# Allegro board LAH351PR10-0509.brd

Outline 153 x 157 mm; copper layers: TOP, GND1, IN1, GND2, IN2, GND3, VCC, IN3, GND4, IN4, GND5, BOTTOM. Coordinates in mm from the lower left corner of the outline.
Outline path: 0,137.03 arc(0.01,137.4) 0.03,137.76 0.37,141.89 arc(0.52,142.22) 0.86,142.35 2,142.35 arc(3.25,143.6) 2,144.85 1.15,144.85 arc(0.78,145.01) 0.65,145.39 0.66,145.54 arc(0.82,145.87) 1.16,146 4.55,146 arc(4.84,145.96) 5.1,145.84 11.6,141.56 arc(11.86,141.44) 12.15,141.4 23.59,141.4 arc(23.78,141.44) 23.95,141.55 26.65,144.25 arc(26.76,144.42) 26.8,144.61 26.8,156.5 arc(26.95,156.85) 27.3,157 31.55,157 arc(31.89,156.87) 32.05,156.55 arc(32.21,156.23) 32.55,156.1 57.55,156.1 arc(57.89,156.23) 58.05,156.55 arc(58.21,156.87) 58.55,157 62.4,157 arc(62.75,156.85) 62.9,156.5 62.9,152.5 arc(63.05,152.15) 63.4,152 74.77,152 arc(74.9,152.02) 75.02,152.07 83.44,156.93 arc(83.56,156.98) 83.69,157 143.8,157 arc(144.15,156.85) 144.3,156.5 144.3,151.4 arc(144.15,151.05) 143.8,150.9 142.89,150.9 arc(141.59,149.6) 142.89,148.3 143.8,148.3 arc(144.15,148.15) 144.3,147.8 144.3,147 arc(144.45,146.65) 144.8,146.5 152.5,146.5 arc(152.85,146.35) 153,146 153,20.2 arc(152.85,19.85) 152.5,19.7 140.7,19.7 arc(140.35,19.55) 140.2,19.2 140.2,2.69 arc(140.05,2.33) 139.7,2.18 138.52,2.18 arc(138.17,2.33) 138.03,2.69 138.03,6.55 arc(138.07,6.7) 138.18,6.81 arc(138.24,7.28) 137.77,7.22 arc(137.66,7.11) 137.51,7.07 117.29,7.07 arc(117.14,7.11) 117.03,7.22 arc(116.56,7.28) 116.62,6.81 arc(116.73,6.7) 116.77,6.55 116.77,2.69 arc(116.63,2.33) 116.28,2.18 113.72,2.18 arc(113.37,2.33) 113.23,2.69 113.23,6.55 arc(113.27,6.7) 113.38,6.81 arc(113.44,7.28) 112.97,7.22 arc(112.86,7.11) 112.71,7.07 92.49,7.07 arc(92.34,7.11) 92.23,7.22 arc(91.76,7.28) 91.82,6.81 arc(91.93,6.7) 91.97,6.55 91.97,2.69 arc(91.85,2.35) 91.54,2.19 arc(91.22,2.02) 91.1,1.69 91.1,0.5 arc(90.95,0.15) 90.6,0 0.5,0 arc(0.15,0.15) 0,0.5 0,137.03 ; 85.5,2.5 arc(87,4) 88.5,2.5 88.5,1.7 arc(88.35,1.35) 88,1.2 86,1.2 arc(85.65,1.35) 85.5,1.7 85.5,2.5

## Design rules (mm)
net group ADC_IN_: nets ADC_IN_N ADC_IN_P
net group ADC_IN__RC: nets ADC_IN_N_RC ADC_IN_P_RC
net group CDRA_: nets CDRA_CLK CDRA_DAT
net group CORE_V1: nets CORE_V1N CORE_V1P
net group CORE_V2: nets CORE_V2N CORE_V2P
net group CORE_V3: nets CORE_V3N CORE_V3P
net group CORE_V4: nets CORE_V4N CORE_V4P
net group CORE_V5: nets CORE_V5N CORE_V5P
net group CORE_V6: nets CORE_V6N CORE_V6P
net group CPU_DDC1: nets CPU_DDC1CLK CPU_DDC1DATA
net group CSI_CHG: nets CSIN_CHG CSIP_CHG
net group CSO_CHG: nets CSON_CHG CSOP_CHG
net group CSS_B+: nets CSSN_B+ CSSP_B+
net group DDR-ALERT_8: nets DDR_A_ALERT# DDR_B_ALERT#
net group DDR_RST: nets DDR_DRAMRST#_R H_DRAMRST#
net group DDRB-CLK: nets DDR_B_CLK0 DDR_B_CLK#0
net group DIFFPAIR1: nets XTALIN XTALOUT
net group DIFFPAIR120: nets CPU_DDC2CLK CPU_DDC2DATA
net group DIFFPAIR121: nets EDP_TXN0_PCH EDP_TXP0_PCH
net group DIFFPAIR122: nets EDP_TXN1_PCH EDP_TXP1_PCH
net group DIFFPAIR123: nets EDP_TXN2_PCH EDP_TXP2_PCH
net group DIFFPAIR124: nets EDP_AUXN_PCH EDP_AUXP_PCH
net group DIFFPAIR125: nets EDP_TXN3_PCH EDP_TXP3_PCH
net group DIFFPAIR126: nets DDR_A_CLK0 DDR_A_CLK#0
net group EC_ESB_: nets EC_ESB_CLK EC_ESB_DAT
net group HDMI_CTRL_: nets HDMI_CTRL_CLK HDMI_CTRL_DAT
net group HDMI_CTRL__R: nets HDMI_CTRL_CLK_R HDMI_CTRL_DAT_R
net group I2C: nets TBTA_I2C_INT TBTA_I2C_INT_R
net group I2C_: nets I2C_CLK I2C_DAT
net group I2C_0_S: nets I2C_0_SCL I2C_0_SDA
net group I2C_0_S_R: nets I2C_0_SCL_R I2C_0_SDA_R
net group I2CC_S: nets I2CC_SCL I2CC_SDA
net group ISEN1_CHG: nets ISEN1N_CHG ISEN1P_CHG
net group ISH_I2C0_S: nets ISH_I2C0_SCL ISH_I2C0_SDA
net group ISL95338_S: nets ISL95338_SCL ISL95338_SDA
net group MIC_: nets MIC_CLK MIC_DATA
net group PCH_CPU_BCLK_: nets PCH_CPU_BCLK_N PCH_CPU_BCLK_P
net group PCH_SMB: nets PCH_SMBCLK PCH_SMBDATA
net group PCIE_RCOMP: nets PCIE_RCOMPN PCIE_RCOMPP
net group PEG_CLK: nets CLK_PEG_N0 CLK_PEG_P0
net group REMOTE1: nets REMOTE1+ REMOTE1-
net group REMOTE2: nets REMOTE2+ REMOTE2-
net group REMOTE3: nets REMOTE3+ REMOTE3-
net group S_CHG: nets SCL_CHG SDA_CHG
net group S_GPU: nets SCL_GPU SDA_GPU
net group SH_IN_3: nets SH_IN_N3 SH_IN_P3
net group SH_IN_4: nets SH_IN_N4 SH_IN_P4
net group SML0: nets SML0CLK SML0DATA
net group SML1: nets SML1CLK SML1DATA
net group TBT_I2C_S: nets TBT_I2C_SCL TBT_I2C_SDA
net group TBT_I2C_S_R: nets TBT_I2C_SCL_R TBT_I2C_SDA_R
net group TBTA_DIG_AUD_: nets TBTA_DIG_AUD_N TBTA_DIG_AUD_P
net group TBTA_I2C_S1_R: nets TBTA_I2C_SCL1_R TBTA_I2C_SDA1_R
net group TP_: nets TP_CLK TP_DATA
net group TP__R: nets TP_CLK_R TP_DATA_R
net group UART: nets UART_2_PRXD_DTXD UART_2_PTXD_DRXD
net group USB20_N3: nets USB20_N3 USB20_N3_R
net group USB20_P3: nets USB20_P3 USB20_P3_R
net group VIN1: nets VIN1N VIN1P
net group VIN2: nets VIN2N VIN2P
net group DDR_COMP: nets DDR_RCOMP0 DDR_RCOMP1 DDR_RCOMP2
net group DDRA-D0: nets DDR_A_D0 DDR_A_D1 DDR_A_D2 DDR_A_D3 DDR_A_D4 DDR_A_D5 DDR_A_D6 DDR_A_D7
net group DDRA-D1: nets DDR_A_D8 DDR_A_D9 DDR_A_D10 DDR_A_D11 DDR_A_D12 DDR_A_D13 DDR_A_D14 DDR_A_D15
net group DDRA-D2: nets DDR_A_D16 DDR_A_D17 DDR_A_D18 DDR_A_D19 DDR_A_D20 DDR_A_D21 DDR_A_D22 DDR_A_D23
net group DDRA-D3: nets DDR_A_D24 DDR_A_D25 DDR_A_D26 DDR_A_D27 DDR_A_D28 DDR_A_D29 DDR_A_D30 DDR_A_D31
net group DDRA-D4: nets DDR_A_D32 DDR_A_D33 DDR_A_D34 DDR_A_D35 DDR_A_D36 DDR_A_D37 DDR_A_D38 DDR_A_D39
net group DDRA-D5: nets DDR_A_D40 DDR_A_D41 DDR_A_D42 DDR_A_D43 DDR_A_D44 DDR_A_D45 DDR_A_D46 DDR_A_D47
net group DDRA-D6: nets DDR_A_D48 DDR_A_D49 DDR_A_D50 DDR_A_D51 DDR_A_D52 DDR_A_D53 DDR_A_D54 DDR_A_D55
net group DDRA-D7: nets DDR_A_D56 DDR_A_D57 DDR_A_D58 DDR_A_D59 DDR_A_D60 DDR_A_D61 DDR_A_D62 DDR_A_D63
net group DDRA-DQS: nets DDR_A_DQS0 DDR_A_DQS1 DDR_A_DQS2 DDR_A_DQS3 DDR_A_DQS4 DDR_A_DQS5 DDR_A_DQS6 DDR_A_DQS7 DDR_A_DQS#0 DDR_A_DQS#1 DDR_A_DQS#2 DDR_A_DQS#3 DDR_A_DQS#4 DDR_A_DQS#5 DDR_A_DQS#6 DDR_A_DQS#7
net group DDRA_ADD: nets DDR_A_ACT# DDR_A_BA0 DDR_A_BA1 DDR_A_BG0 DDR_A_BG1 DDR_A_MA0 DDR_A_MA1 DDR_A_MA2 DDR_A_MA3 DDR_A_MA4 DDR_A_MA5 DDR_A_MA6 DDR_A_MA7 DDR_A_MA8 DDR_A_MA9 DDR_A_MA10 DDR_A_MA11 DDR_A_MA12 DDR_A_MA13 DDR_A_MA14 DDR_A_MA15 DDR_A_MA16 DDR_A_PARITY
net group DDRA_CTRL: nets DDR_A_CKE0 DDR_A_CS#0 DDR_A_ODT0
net group DDRB-D0: nets DDR_B_D0 DDR_B_D1 DDR_B_D2 DDR_B_D3 DDR_B_D4 DDR_B_D5 DDR_B_D6 DDR_B_D7
net group DDRB-D1: nets DDR_B_D8 DDR_B_D9 DDR_B_D10 DDR_B_D11 DDR_B_D12 DDR_B_D13 DDR_B_D14 DDR_B_D15
net group DDRB-D2: nets DDR_B_D16 DDR_B_D17 DDR_B_D18 DDR_B_D19 DDR_B_D20 DDR_B_D21 DDR_B_D22 DDR_B_D23
net group DDRB-D3: nets DDR_B_D24 DDR_B_D25 DDR_B_D26 DDR_B_D27 DDR_B_D28 DDR_B_D29 DDR_B_D30 DDR_B_D31
net group DDRB-D4: nets DDR_B_D32 DDR_B_D33 DDR_B_D34 DDR_B_D35 DDR_B_D36 DDR_B_D37 DDR_B_D38 DDR_B_D39
net group DDRB-D5: nets DDR_B_D40 DDR_B_D41 DDR_B_D42 DDR_B_D43 DDR_B_D44 DDR_B_D45 DDR_B_D46 DDR_B_D47
net group DDRB-D6: nets DDR_B_D48 DDR_B_D49 DDR_B_D50 DDR_B_D51 DDR_B_D52 DDR_B_D53 DDR_B_D54 DDR_B_D55
net group DDRB-D7: nets DDR_B_D56 DDR_B_D57 DDR_B_D58 DDR_B_D59 DDR_B_D60 DDR_B_D61 DDR_B_D62 DDR_B_D63
net group DDRB-DQS: nets DDR_B_DQS0 DDR_B_DQS1 DDR_B_DQS2 DDR_B_DQS3 DDR_B_DQS4 DDR_B_DQS5 DDR_B_DQS6 DDR_B_DQS7 DDR_B_DQS#0 DDR_B_DQS#1 DDR_B_DQS#2 DDR_B_DQS#3 DDR_B_DQS#4 DDR_B_DQS#5 DDR_B_DQS#6 DDR_B_DQS#7
net group DDRB_ADD: nets DDR_B_ACT# DDR_B_BA0 DDR_B_BA1 DDR_B_BG0 DDR_B_BG1 DDR_B_MA0 DDR_B_MA1 DDR_B_MA2 DDR_B_MA3 DDR_B_MA4 DDR_B_MA5 DDR_B_MA6 DDR_B_MA7 DDR_B_MA8 DDR_B_MA9 DDR_B_MA10 DDR_B_MA11 DDR_B_MA12 DDR_B_MA13 DDR_B_MA14 DDR_B_MA15 DDR_B_MA16 DDR_B_PARITY
net group DDRB_CTRL: nets DDR_B_CKE0 DDR_B_CS#0 DDR_B_ODT0
net group DMI: nets DMI_CRX_PTX_N0 DMI_CRX_PTX_N1 DMI_CRX_PTX_N2 DMI_CRX_PTX_N3 DMI_CRX_PTX_P0 DMI_CRX_PTX_P1 DMI_CRX_PTX_P2 DMI_CRX_PTX_P3 DMI_CTX_PRX_N0 DMI_CTX_PRX_N1 DMI_CTX_PRX_N2 DMI_CTX_PRX_N3 DMI_CTX_PRX_P0 DMI_CTX_PRX_P1 DMI_CTX_PRX_P2 DMI_CTX_PRX_P3
net group DP: nets CPU_DP1_AUXN CPU_DP1_AUXN_C CPU_DP1_AUXP CPU_DP1_AUXP_C CPU_DP1_HPD CPU_DP1_N0 CPU_DP1_N0_C CPU_DP1_N1 CPU_DP1_N1_C CPU_DP1_N2 CPU_DP1_N2_C CPU_DP1_N3 CPU_DP1_N3_C CPU_DP1_P0 CPU_DP1_P0_C CPU_DP1_P1 CPU_DP1_P1_C CPU_DP1_P2 CPU_DP1_P2_C CPU_DP1_P3 CPU_DP1_P3_C CPU_DP2_AUXN CPU_DP2_AUXN_C CPU_DP2_AUXP CPU_DP2_AUXP_C CPU_DP2_HPD CPU_DP2_N0 CPU_DP2_N0_C CPU_DP2_N1 CPU_DP2_N1_C CPU_DP2_N2 CPU_DP2_N2_C CPU_DP2_N3 CPU_DP2_N3_C CPU_DP2_P0 CPU_DP2_P0_C CPU_DP2_P1 CPU_DP2_P1_C CPU_DP2_P2 CPU_DP2_P2_C CPU_DP2_P3 CPU_DP2_P3_C
net group EDP: nets EDP_AUXN_C EDP_AUXP_C EDP_TXN0_C EDP_TXN1_C EDP_TXN2_C EDP_TXN3_C EDP_TXP0_C EDP_TXP1_C EDP_TXP2_C EDP_TXP3_C
net group GPU_A_CLK: nets FB_A_CLK0 FB_A_CLK1 FB_A_CLK#0 FB_A_CLK#1
net group GPU_A_CMD: nets FB_A_CMD0 FB_A_CMD1 FB_A_CMD2 FB_A_CMD3 FB_A_CMD4 FB_A_CMD5 FB_A_CMD6 FB_A_CMD7 FB_A_CMD8 FB_A_CMD9 FB_A_CMD10 FB_A_CMD11 FB_A_CMD12 FB_A_CMD13 FB_A_CMD14 FB_A_CMD15 FB_A_CMD16 FB_A_CMD17 FB_A_CMD18 FB_A_CMD19 FB_A_CMD20 FB_A_CMD21 FB_A_CMD22 FB_A_CMD23 FB_A_CMD24 FB_A_CMD25 FB_A_CMD26 FB_A_CMD27 FB_A_CMD28 FB_A_CMD29 FB_A_CMD30 FB_A_CMD31 FB_A_CMD32 FB_A_CMD33
net group GPU_A_D0: nets FB_A_D0 FB_A_D1 FB_A_D2 FB_A_D3 FB_A_D4 FB_A_D5 FB_A_D6 FB_A_D7
net group GPU_A_D1: nets FB_A_D8 FB_A_D9 FB_A_D10 FB_A_D11 FB_A_D12 FB_A_D13 FB_A_D14 FB_A_D15
net group GPU_A_D2: nets FB_A_D16 FB_A_D17 FB_A_D18 FB_A_D19 FB_A_D20 FB_A_D21 FB_A_D22 FB_A_D23
net group GPU_A_D3: nets FB_A_D24 FB_A_D25 FB_A_D26 FB_A_D27 FB_A_D28 FB_A_D29 FB_A_D30 FB_A_D31
net group GPU_A_D4: nets FB_A_D32 FB_A_D33 FB_A_D34 FB_A_D35 FB_A_D36 FB_A_D37 FB_A_D38 FB_A_D39
net group GPU_A_D5: nets FB_A_D40 FB_A_D41 FB_A_D42 FB_A_D43 FB_A_D44 FB_A_D45 FB_A_D46 FB_A_D47
net group GPU_A_D6: nets FB_A_D48 FB_A_D49 FB_A_D50 FB_A_D51 FB_A_D52 FB_A_D53 FB_A_D54 FB_A_D55
net group GPU_A_D7: nets FB_A_D56 FB_A_D57 FB_A_D58 FB_A_D59 FB_A_D60 FB_A_D61 FB_A_D62 FB_A_D63
net group GPU_A_DBI: nets FB_A_DBI0 FB_A_DBI1 FB_A_DBI2 FB_A_DBI3 FB_A_DBI4 FB_A_DBI5 FB_A_DBI6 FB_A_DBI7
net group GPU_A_EDC: nets FB_A_EDC0 FB_A_EDC1 FB_A_EDC2 FB_A_EDC3 FB_A_EDC4 FB_A_EDC5 FB_A_EDC6 FB_A_EDC7
net group GPU_A_WCK: nets FB_A_WCK01 FB_A_WCK23 FB_A_WCK45 FB_A_WCK67 FB_A_WCK#01 FB_A_WCK#23 FB_A_WCK#45 FB_A_WCK#67 FB_A_WCKB01 FB_A_WCKB23 FB_A_WCKB45 FB_A_WCKB67 FB_A_WCKB#01 FB_A_WCKB#23 FB_A_WCKB#45 FB_A_WCKB#67
net group GPU_B_CLK: nets FB_B_CLK0 FB_B_CLK1 FB_B_CLK#0 FB_B_CLK#1
net group GPU_B_CMD: nets FB_B_CMD0 FB_B_CMD1 FB_B_CMD2 FB_B_CMD3 FB_B_CMD4 FB_B_CMD5 FB_B_CMD6 FB_B_CMD7 FB_B_CMD8 FB_B_CMD9 FB_B_CMD10 FB_B_CMD11 FB_B_CMD12 FB_B_CMD13 FB_B_CMD14 FB_B_CMD15 FB_B_CMD16 FB_B_CMD17 FB_B_CMD18 FB_B_CMD19 FB_B_CMD20 FB_B_CMD21 FB_B_CMD22 FB_B_CMD23 FB_B_CMD24 FB_B_CMD25 FB_B_CMD26 FB_B_CMD27 FB_B_CMD28 FB_B_CMD29 FB_B_CMD30 FB_B_CMD31 FB_B_CMD32 FB_B_CMD33
net group GPU_B_D0: nets FB_B_D0 FB_B_D1 FB_B_D2 FB_B_D3 FB_B_D4 FB_B_D5 FB_B_D6 FB_B_D7
net group GPU_B_D1: nets FB_B_D8 FB_B_D9 FB_B_D10 FB_B_D11 FB_B_D12 FB_B_D13 FB_B_D14 FB_B_D15
net group GPU_B_D2: nets FB_B_D16 FB_B_D17 FB_B_D18 FB_B_D19 FB_B_D20 FB_B_D21 FB_B_D22 FB_B_D23
net group GPU_B_D3: nets FB_B_D24 FB_B_D25 FB_B_D26 FB_B_D27 FB_B_D28 FB_B_D29 FB_B_D30 FB_B_D31
net group GPU_B_D4: nets FB_B_D32 FB_B_D33 FB_B_D34 FB_B_D35 FB_B_D36 FB_B_D37 FB_B_D38 FB_B_D39
net group GPU_B_D5: nets FB_B_D40 FB_B_D41 FB_B_D42 FB_B_D43 FB_B_D44 FB_B_D45 FB_B_D46 FB_B_D47
net group GPU_B_D6: nets FB_B_D48 FB_B_D49 FB_B_D50 FB_B_D51 FB_B_D52 FB_B_D53 FB_B_D54 FB_B_D55
net group GPU_B_D7: nets FB_B_D56 FB_B_D57 FB_B_D58 FB_B_D59 FB_B_D60 FB_B_D61 FB_B_D62 FB_B_D63
net group GPU_B_DBI: nets FB_B_DBI0 FB_B_DBI1 FB_B_DBI2 FB_B_DBI3 FB_B_DBI4 FB_B_DBI5 FB_B_DBI6 FB_B_DBI7
net group GPU_B_EDC: nets FB_B_EDC0 FB_B_EDC1 FB_B_EDC2 FB_B_EDC3 FB_B_EDC4 FB_B_EDC5 FB_B_EDC6 FB_B_EDC7
net group GPU_B_WCK: nets FB_B_WCK01 FB_B_WCK23 FB_B_WCK45 FB_B_WCK67 FB_B_WCK#01 FB_B_WCK#23 FB_B_WCK#45 FB_B_WCK#67
net group GPU_C_CLK: nets FB_C_CLK0 FB_C_CLK1 FB_C_CLK#0 FB_C_CLK#1
net group GPU_C_CMD: nets FB_C_CMD0 FB_C_CMD1 FB_C_CMD2 FB_C_CMD3 FB_C_CMD4 FB_C_CMD5 FB_C_CMD6 FB_C_CMD7 FB_C_CMD8 FB_C_CMD9 FB_C_CMD10 FB_C_CMD11 FB_C_CMD12 FB_C_CMD13 FB_C_CMD14 FB_C_CMD15 FB_C_CMD16 FB_C_CMD17 FB_C_CMD18 FB_C_CMD19 FB_C_CMD20 FB_C_CMD21 FB_C_CMD22 FB_C_CMD23 FB_C_CMD24 FB_C_CMD25 FB_C_CMD26 FB_C_CMD27 FB_C_CMD28 FB_C_CMD29 FB_C_CMD30 FB_C_CMD31 FB_C_CMD32 FB_C_CMD33
net group GPU_C_D0: nets FB_C_D0 FB_C_D1 FB_C_D2 FB_C_D3 FB_C_D4 FB_C_D5 FB_C_D6 FB_C_D7
net group GPU_C_D1: nets FB_C_D8 FB_C_D9 FB_C_D10 FB_C_D11 FB_C_D12 FB_C_D13 FB_C_D14 FB_C_D15
net group GPU_C_D2: nets FB_C_D16 FB_C_D17 FB_C_D18 FB_C_D19 FB_C_D20 FB_C_D21 FB_C_D22 FB_C_D23
net group GPU_C_D3: nets FB_C_D24 FB_C_D25 FB_C_D26 FB_C_D27 FB_C_D28 FB_C_D29 FB_C_D30 FB_C_D31
net group GPU_C_D4: nets FB_C_D32 FB_C_D33 FB_C_D34 FB_C_D35 FB_C_D36 FB_C_D37 FB_C_D38 FB_C_D39
net group GPU_C_D5: nets FB_C_D40 FB_C_D41 FB_C_D42 FB_C_D43 FB_C_D44 FB_C_D45 FB_C_D46 FB_C_D47
net group GPU_C_D6: nets FB_C_D48 FB_C_D49 FB_C_D50 FB_C_D51 FB_C_D52 FB_C_D53 FB_C_D54 FB_C_D55
net group GPU_C_D7: nets FB_C_D56 FB_C_D57 FB_C_D58 FB_C_D59 FB_C_D60 FB_C_D61 FB_C_D62 FB_C_D63
net group GPU_C_DBI: nets FB_C_DBI0 FB_C_DBI1 FB_C_DBI2 FB_C_DBI3 FB_C_DBI4 FB_C_DBI5 FB_C_DBI6 FB_C_DBI7
net group GPU_C_EDC: nets FB_C_EDC0 FB_C_EDC1 FB_C_EDC2 FB_C_EDC3 FB_C_EDC4 FB_C_EDC5 FB_C_EDC6 FB_C_EDC7
net group GPU_C_WCK: nets FB_B_WCKB01 FB_B_WCKB23 FB_B_WCKB45 FB_B_WCKB67 FB_B_WCKB#01 FB_B_WCKB#23 FB_B_WCKB#45 FB_B_WCKB#67 FB_C_WCK01 FB_C_WCK23 FB_C_WCK45 FB_C_WCK67 FB_C_WCK#01 FB_C_WCK#23 FB_C_WCK#45 FB_C_WCK#67 FB_C_WCKB01 FB_C_WCKB23 FB_C_WCKB45 FB_C_WCKB67 FB_C_WCKB#01 FB_C_WCKB#23 FB_C_WCKB#45 FB_C_WCKB#67
net group GPU_D_CLK: nets FB_D_CLK0 FB_D_CLK1 FB_D_CLK#0 FB_D_CLK#1
net group GPU_D_CMD: nets FB_D_CMD0 FB_D_CMD1 FB_D_CMD2 FB_D_CMD3 FB_D_CMD4 FB_D_CMD5 FB_D_CMD6 FB_D_CMD7 FB_D_CMD8 FB_D_CMD9 FB_D_CMD10 FB_D_CMD11 FB_D_CMD12 FB_D_CMD13 FB_D_CMD14 FB_D_CMD15 FB_D_CMD16 FB_D_CMD17 FB_D_CMD18 FB_D_CMD19 FB_D_CMD20 FB_D_CMD21 FB_D_CMD22 FB_D_CMD23 FB_D_CMD24 FB_D_CMD25 FB_D_CMD26 FB_D_CMD27 FB_D_CMD28 FB_D_CMD29 FB_D_CMD30 FB_D_CMD31 FB_D_CMD32 FB_D_CMD33
net group GPU_D_D0: nets FB_D_D0 FB_D_D1 FB_D_D2 FB_D_D3 FB_D_D4 FB_D_D5 FB_D_D6 FB_D_D7
net group GPU_D_D1: nets FB_D_D8 FB_D_D9 FB_D_D10 FB_D_D11 FB_D_D12 FB_D_D13 FB_D_D14 FB_D_D15
net group GPU_D_D2: nets FB_D_D16 FB_D_D17 FB_D_D18 FB_D_D19 FB_D_D20 FB_D_D21 FB_D_D22 FB_D_D23
net group GPU_D_D3: nets FB_D_D24 FB_D_D25 FB_D_D26 FB_D_D27 FB_D_D28 FB_D_D29 FB_D_D30 FB_D_D31
net group GPU_D_D4: nets FB_D_D32 FB_D_D33 FB_D_D34 FB_D_D35 FB_D_D36 FB_D_D37 FB_D_D38 FB_D_D39
net group GPU_D_D5: nets FB_D_D40 FB_D_D41 FB_D_D42 FB_D_D43 FB_D_D44 FB_D_D45 FB_D_D46 FB_D_D47
net group GPU_D_D6: nets FB_D_D48 FB_D_D49 FB_D_D50 FB_D_D51 FB_D_D52 FB_D_D53 FB_D_D54 FB_D_D55
net group GPU_D_D7: nets FB_D_D56 FB_D_D57 FB_D_D58 FB_D_D59 FB_D_D60 FB_D_D61 FB_D_D62 FB_D_D63
net group GPU_D_DBI: nets FB_D_DBI0 FB_D_DBI1 FB_D_DBI2 FB_D_DBI3 FB_D_DBI4 FB_D_DBI5 FB_D_DBI6 FB_D_DBI7
net group GPU_D_EDC: nets FB_D_EDC0 FB_D_EDC1 FB_D_EDC2 FB_D_EDC3 FB_D_EDC4 FB_D_EDC5 FB_D_EDC6 FB_D_EDC7
net group GPU_D_WCK: nets FB_D_WCK01 FB_D_WCK23 FB_D_WCK45 FB_D_WCK67 FB_D_WCK#01 FB_D_WCK#23 FB_D_WCK#45 FB_D_WCK#67 FB_D_WCKB01 FB_D_WCKB23 FB_D_WCKB45 FB_D_WCKB67 FB_D_WCKB#01 FB_D_WCKB#23 FB_D_WCKB#45 FB_D_WCKB#67
net group HDA: nets HDA_BIT_CLK HDA_BIT_CLK_R HDA_RST# HDA_RST#_R HDA_SDIN HDA_SDOUT HDA_SDOUT_R HDA_SYNC HDA_SYNC_R
net group HDMI: nets GPU_HDMI_CLKN GPU_HDMI_CLKP GPU_HDMI_CTRL_CLK GPU_HDMI_CTRL_DAT GPU_HDMI_TX_N0 GPU_HDMI_TX_N1 GPU_HDMI_TX_N2 GPU_HDMI_TX_P0 GPU_HDMI_TX_P1 GPU_HDMI_TX_P2 HDMI_C_CLKN HDMI_C_CLKP HDMI_C_TX_N0 HDMI_C_TX_N1 HDMI_C_TX_N2 HDMI_C_TX_P0 HDMI_C_TX_P1 HDMI_C_TX_P2 HDMI_CLKN HDMI_CLKP HDMI_L_CLKN HDMI_L_CLKP HDMI_L_TX_N0 HDMI_L_TX_N1 HDMI_L_TX_N2 HDMI_L_TX_P0 HDMI_L_TX_P1 HDMI_L_TX_P2 HDMI_TX_N0 HDMI_TX_N1 HDMI_TX_N2 HDMI_TX_P0 HDMI_TX_P1 HDMI_TX_P2
net group MDP: nets DISP_CLK_AUXP_CONN DISP_DAT_AUXN_CONN GPU_DP_AUXN GPU_DP_AUXN_C GPU_DP_AUXN_R GPU_DP_AUXP GPU_DP_AUXP_C GPU_DP_AUXP_R GPU_DP_N0 GPU_DP_N0_C GPU_DP_N1 GPU_DP_N1_C GPU_DP_N2 GPU_DP_N2_C GPU_DP_N3 GPU_DP_N3_C GPU_DP_P0 GPU_DP_P0_C GPU_DP_P1 GPU_DP_P1_C GPU_DP_P2 GPU_DP_P2_C GPU_DP_P3 GPU_DP_P3_C
net group PCIE: nets PCIE_PRX_C_DTX_N17 PCIE_PRX_C_DTX_N18 PCIE_PRX_C_DTX_N19 PCIE_PRX_C_DTX_N20 PCIE_PRX_C_DTX_P17 PCIE_PRX_C_DTX_P18 PCIE_PRX_C_DTX_P19 PCIE_PRX_C_DTX_P20 PCIE_PRX_DTX_N9 PCIE_PRX_DTX_N10 PCIE_PRX_DTX_N11 PCIE_PRX_DTX_N12 PCIE_PRX_DTX_N15 PCIE_PRX_DTX_N16 PCIE_PRX_DTX_N17 PCIE_PRX_DTX_N18 PCIE_PRX_DTX_N19 PCIE_PRX_DTX_N20 PCIE_PRX_DTX_N21 PCIE_PRX_DTX_N22 PCIE_PRX_DTX_N23 PCIE_PRX_DTX_N24 PCIE_PRX_DTX_P9 PCIE_PRX_DTX_P10 PCIE_PRX_DTX_P11 PCIE_PRX_DTX_P12 PCIE_PRX_DTX_P15 PCIE_PRX_DTX_P16 PCIE_PRX_DTX_P17 PCIE_PRX_DTX_P18 PCIE_PRX_DTX_P19 PCIE_PRX_DTX_P20 PCIE_PRX_DTX_P21 PCIE_PRX_DTX_P22 PCIE_PRX_DTX_P23 PCIE_PRX_DTX_P24 PCIE_PTX_C_DRX_N9 PCIE_PTX_C_DRX_N10 PCIE_PTX_C_DRX_N11 PCIE_PTX_C_DRX_N12 PCIE_PTX_C_DRX_N17 PCIE_PTX_C_DRX_N18 PCIE_PTX_C_DRX_N19 PCIE_PTX_C_DRX_N20 PCIE_PTX_C_DRX_N21 PCIE_PTX_C_DRX_N22 PCIE_PTX_C_DRX_N23 PCIE_PTX_C_DRX_N24 PCIE_PTX_C_DRX_P9 PCIE_PTX_C_DRX_P10 PCIE_PTX_C_DRX_P11 PCIE_PTX_C_DRX_P12 PCIE_PTX_C_DRX_P17 PCIE_PTX_C_DRX_P18 PCIE_PTX_C_DRX_P19 PCIE_PTX_C_DRX_P20 PCIE_PTX_C_DRX_P21 PCIE_PTX_C_DRX_P22 PCIE_PTX_C_DRX_P23 PCIE_PTX_C_DRX_P24 PCIE_PTX_DRX_N9 PCIE_PTX_DRX_N10 PCIE_PTX_DRX_N11 PCIE_PTX_DRX_N12 PCIE_PTX_DRX_N15 PCIE_PTX_DRX_N16 PCIE_PTX_DRX_N17 PCIE_PTX_DRX_N18 PCIE_PTX_DRX_N19 PCIE_PTX_DRX_N20 PCIE_PTX_DRX_N21 PCIE_PTX_DRX_N22 PCIE_PTX_DRX_N23 PCIE_PTX_DRX_N24 PCIE_PTX_DRX_P9 PCIE_PTX_DRX_P10 PCIE_PTX_DRX_P11 PCIE_PTX_DRX_P12 PCIE_PTX_DRX_P15 PCIE_PTX_DRX_P16 PCIE_PTX_DRX_P17 PCIE_PTX_DRX_P18 PCIE_PTX_DRX_P19 PCIE_PTX_DRX_P20 PCIE_PTX_DRX_P21 PCIE_PTX_DRX_P22 PCIE_PTX_DRX_P23 PCIE_PTX_DRX_P24
net group PEG: nets PEG_CRX_C_GTX_N0 PEG_CRX_C_GTX_N1 PEG_CRX_C_GTX_N2 PEG_CRX_C_GTX_N3 PEG_CRX_C_GTX_N4 PEG_CRX_C_GTX_N5 PEG_CRX_C_GTX_N6 PEG_CRX_C_GTX_N7 PEG_CRX_C_GTX_P0 PEG_CRX_C_GTX_P1 PEG_CRX_C_GTX_P2 PEG_CRX_C_GTX_P3 PEG_CRX_C_GTX_P4 PEG_CRX_C_GTX_P5 PEG_CRX_C_GTX_P6 PEG_CRX_C_GTX_P7 PEG_CRX_C_RD_GTX_N8 PEG_CRX_C_RD_GTX_N9 PEG_CRX_C_RD_GTX_N10 PEG_CRX_C_RD_GTX_N11 PEG_CRX_C_RD_GTX_P8 PEG_CRX_C_RD_GTX_P9 PEG_CRX_C_RD_GTX_P10 PEG_CRX_C_RD_GTX_P11 PEG_CRX_GTX_N0 PEG_CRX_GTX_N1 PEG_CRX_GTX_N2 PEG_CRX_GTX_N3 PEG_CRX_GTX_N4 PEG_CRX_GTX_N5 PEG_CRX_GTX_N6 PEG_CRX_GTX_N7 PEG_CRX_GTX_N8 PEG_CRX_GTX_N9 PEG_CRX_GTX_N10 PEG_CRX_GTX_N11 PEG_CRX_GTX_P0 PEG_CRX_GTX_P1 PEG_CRX_GTX_P2 PEG_CRX_GTX_P3 PEG_CRX_GTX_P4 PEG_CRX_GTX_P5 PEG_CRX_GTX_P6 PEG_CRX_GTX_P7 PEG_CRX_GTX_P8 PEG_CRX_GTX_P9 PEG_CRX_GTX_P10 PEG_CRX_GTX_P11 PEG_CRX_RD_GTX_N8 PEG_CRX_RD_GTX_N9 PEG_CRX_RD_GTX_N10 PEG_CRX_RD_GTX_N11 PEG_CRX_RD_GTX_P8 PEG_CRX_RD_GTX_P9 PEG_CRX_RD_GTX_P10 PEG_CRX_RD_GTX_P11 PEG_CTX_C_GRX_N0 PEG_CTX_C_GRX_N1 PEG_CTX_C_GRX_N2 PEG_CTX_C_GRX_N3 PEG_CTX_C_GRX_N4 PEG_CTX_C_GRX_N5 PEG_CTX_C_GRX_N6 PEG_CTX_C_GRX_N7 PEG_CTX_C_GRX_N8 PEG_CTX_C_GRX_N9 PEG_CTX_C_GRX_N10 PEG_CTX_C_GRX_N11 PEG_CTX_C_GRX_P0 PEG_CTX_C_GRX_P1 PEG_CTX_C_GRX_P2 PEG_CTX_C_GRX_P3 PEG_CTX_C_GRX_P4 PEG_CTX_C_GRX_P5 PEG_CTX_C_GRX_P6 PEG_CTX_C_GRX_P7 PEG_CTX_C_GRX_P8 PEG_CTX_C_GRX_P9 PEG_CTX_C_GRX_P10 PEG_CTX_C_GRX_P11 PEG_CTX_GRX_N0 PEG_CTX_GRX_N1 PEG_CTX_GRX_N2 PEG_CTX_GRX_N3 PEG_CTX_GRX_N4 PEG_CTX_GRX_N5 PEG_CTX_GRX_N6 PEG_CTX_GRX_N7 PEG_CTX_GRX_N8 PEG_CTX_GRX_N9 PEG_CTX_GRX_N10 PEG_CTX_GRX_N11 PEG_CTX_GRX_P0 PEG_CTX_GRX_P1 PEG_CTX_GRX_P2 PEG_CTX_GRX_P3 PEG_CTX_GRX_P4 PEG_CTX_GRX_P5 PEG_CTX_GRX_P6 PEG_CTX_GRX_P7 PEG_CTX_GRX_P8 PEG_CTX_GRX_P9 PEG_CTX_GRX_P10 PEG_CTX_GRX_P11
net group PLATFORM-CLK: nets CLK_PCIE_N1 CLK_PCIE_N3 CLK_PCIE_N4 CLK_PCIE_N5 CLK_PCIE_N7 CLK_PCIE_P1 CLK_PCIE_P3 CLK_PCIE_P4 CLK_PCIE_P5 CLK_PCIE_P7 CLK_PEG_N6 CLK_PEG_P6 CPU_24MHZ_N CPU_24MHZ_P PCH_CPU_PCIBCLK_N PCH_CPU_PCIBCLK_P PCH_XDP_CLK_N PCH_XDP_CLK_P
net group RTC: nets EC_RTCRST EC_SRTCRST PCH_RTCRST# PCH_RTCX1 PCH_RTCX2 PCH_SRTCRST#
net group SMBUS: nets CLK_SMB DAT_SMB DEMB0 DEMB1 EC_SMB_CK1 EC_SMB_CK2 EC_SMB_DA1 EC_SMB_DA2 VGA_SMB_CK2 VGA_SMB_DA2
net group SPI: nets DGPU_ROM_SCLK DGPU_ROM_SI DGPU_ROM_SO_R PCH_SPI_0_CLK PCH_SPI_0_CLK_R PCH_SPI_0_CS# PCH_SPI_0_HOLD# PCH_SPI_0_HOLD#_R PCH_SPI_0_SI PCH_SPI_0_SI_R PCH_SPI_0_SO PCH_SPI_0_SO_R PCH_SPI_0_WP# PCH_SPI_0_WP#_R PD_EE_CLK PD_EE_CS_N PD_EE_DI PD_EE_DO ROM_CS# ROM_CS#_R ROM_SCLK ROM_SI ROM_SO SPI_CLK SPI_CS# SPI_MOSI TBT_EE_CLK TBT_EE_CS_N TBT_EE_DI TBT_EE_DO TBT_EE_WP_N TBT_HOLD_N
net group SVID: nets VR_SVID_ALERT# VR_SVID_CLK VR_SVID_DATA
net group TBT: nets TBT_A_AUX_N TBT_A_AUX_N_C TBT_A_AUX_P TBT_A_AUX_P_C TBT_A_TRX_DTX_N0 TBT_A_TRX_DTX_N1 TBT_A_TRX_DTX_P0 TBT_A_TRX_DTX_P1 TBT_A_TTX_C_DRX_N0 TBT_A_TTX_C_DRX_N1 TBT_A_TTX_C_DRX_P0 TBT_A_TTX_C_DRX_P1 TBT_A_TTX_DRX_N0 TBT_A_TTX_DRX_N1 TBT_A_TTX_DRX_P0 TBT_A_TTX_DRX_P1
net group USB20: nets TBT_A_USB20_L_NB TBT_A_USB20_L_NT TBT_A_USB20_L_PB TBT_A_USB20_L_PT TBT_A_USB20_N TBT_A_USB20_NB TBT_A_USB20_NT TBT_A_USB20_P TBT_A_USB20_PB TBT_A_USB20_PT USB20_N1 USB20_N2 USB20_N4 USB20_N7 USB20_N7_R USB20_N8 USB20_N9 USB20_N9_R USB20_N10 USB20_N10_R USB20_N11 USB20_N11_R USB20_N14 USB20_P1 USB20_P2 USB20_P4 USB20_P7 USB20_P7_R USB20_P8 USB20_P9 USB20_P9_R USB20_P10 USB20_P10_R USB20_P11 USB20_P11_R USB20_P14
net group USB30: nets USB3_PRX_C_DTX_N8 USB3_PRX_C_DTX_P8 USB3_PRX_DTX_N5 USB3_PRX_DTX_N6 USB3_PRX_DTX_N7 USB3_PRX_DTX_N8 USB3_PRX_DTX_P5 USB3_PRX_DTX_P6 USB3_PRX_DTX_P7 USB3_PRX_DTX_P8 USB3_PTX_DRX_N5 USB3_PTX_DRX_N6 USB3_PTX_DRX_N7 USB3_PTX_DRX_N8 USB3_PTX_DRX_P5 USB3_PTX_DRX_P6 USB3_PTX_DRX_P7 USB3_PTX_DRX_P8
nets with their own width: min track width 0.203; nets +PEX_VDD
nets with their own width: min track width 0.254; nets +1.35VS_VGA FB_VDDQ_SENSE NVVDD_VCC_SENSE NVVDD_VSS_SENSE
nets with their own width: min track width 0.406; nets +FBA_VREFC +FBC_VREFC +FBD_VREFC
nets with their own width: min track width 0.508; nets 1V8_AON_EN 1V8_MAIN_EN 3V3_SYS_EN +1.8VALW +1V8_MAIN +3V3_SYS +5VALW +FBB_VREFC +FBX_PLLAVDD GND
nets with their own width: min track width 1.016; nets +1V8_AON +3VALW +3VS +5VS

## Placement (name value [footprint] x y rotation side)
C2  0.1U_0402_10V6K  [C_0402]  95.84 20.52 0 bottom
C3  2200P_0402_25V7K  [C_0402]  91.14 81.12 180 top
C4  1U_0402_6.3V6K  [C_0402]  86.28 113.82 0 top
C6  0.1U_0402_10V7K  [C_0402]  90.55 107.23 270 top
C7  1U_0402_6.3V6K  [C_0402]  85.28 112.92 90 top
C8  22U_0605_6.3V6M  [C_0603]  90.55 108.27 90 top
C10  0.1U_0402_10V7K  [C_0402]  89.04 113.82 180 top
C11  2.2U_0402_6.3VX5R  [C_0402]  92.84 82.06 90 top
C256  10U_0402_6.3V6M  [C_0402]  63.42 8.92 0 bottom
C257  10U_0603_6.3V6M  [C_0603]  63.18 7.84 0 bottom
C258  0.1U_0402_16V7K  [C_0402]  69.28 14.49 90 bottom
C260  10U_0402_6.3V6M  [C_0402]  72.59 9.36 180 bottom
C261  10U_0603_6.3V6M  [C_0603]  74.61 10.7 270 bottom
C262  10U_0603_6.3V6M  [C_0603]  75.63 14.32 270 bottom
C263  0.1U_0402_10V7K  [C_0402]  74.55 14.07 270 bottom
C264  10U_0603_6.3V6M  [C_0603]  65.53 14.25 90 bottom
C265  0.1U_0402_10V7K  [C_0402]  64.39 14.37 90 bottom
C266  10U_0402_6.3V6M  [C_0402]  104.84 14.65 270 top
C267  10U_0603_6.3V6M  [C_0603]  103.7 14.95 270 top
C268  0.01U_0402_16V  [C_0402]  96.71 15.06 90 top
C269  10U_0603_6.3V6M  [C_0603]  101.09 13.74 0 top
C270  0.1U_0402_10V7K  [C_0402]  101.33 14.82 0 top
C617  33P_0402_50V8J  [C_0402]  92.6 11.01 180 bottom
C618  33P_0402_50V8J  [C_0402]  111.7 12.04 270 bottom
C621  0.047U_0402_16V4Z  [C_0402]  92.6 11.9 180 bottom
C622  22U_0402_6.3V6M  [C_0402]  112.65 12.04 270 bottom
C623  0.047U_0402_16V4Z  [C_0402]  111.7 12.91 90 bottom
C629  33P_0402_50V8J  [C_0402]  119.37 12.16 0 bottom
C630  33P_0402_50V8J  [C_0402]  119.37 11.27 0 bottom
C631  150U_B2_6.3VM_R35M  [C_B2]  114.51 12.41 180 bottom
C632  0.047U_0402_16V4Z  [C_0402]  119.37 13.05 0 bottom
C633  22U_0402_6.3V6M  [C_0402]  128.08 11.32 90 bottom
C634  0.047U_0402_16V4Z  [C_0402]  128.97 11.32 90 bottom
C635  22U_0402_6.3V6M  [C_0402]  92.6 12.79 180 bottom
C636  22U_0402_6.3V6M  [C_0402]  112.65 12.91 90 bottom
C639  22U_0402_6.3V6M  [C_0402]  130.37 12.4 90 bottom
C640  22U_0402_6.3V6M  [C_0402]  131.32 12.4 90 bottom
C641  150U_B2_6.3VM_R35M  [C_B2]  133.25 11.33 180 bottom
C2498  0.1U_0402_10V6K  [C_0402]  62.29 70.69 90 top
C2500  2200P_0402_25V7K  [C_0402]  73.28 69.43 90 top
C2502  2200P_0402_25V7K  [C_0402]  61.34 70.69 90 top
C2504  2200P_0402_25V7K  [C_0402]  59.56 71.61 270 top
C2505  2200P_0402_25V7K  [C_0402]  119.59 64.34 180 bottom
C2506  220P_0402_50V8J  [C_0402]  67.44 9.69 270 bottom
C2507  470P_0402_50V7K  [C_0402]  68.45 9.69 270 bottom
C2510  2200P_0402_25V7K  [C_0402]  58.61 70.69 90 top
C2511  2200P_0402_25V7K  [C_0402]  81.36 103.47 180 bottom
C2512  10U_0603_6.3V6M  [C_0603]  94.36 13.93 90 top
C2513  47U_0603_6.3V6M  [C_0603]  95.63 13.93 90 top
C2514  10U_0603_6.3V6M  [C_0603]  93.09 17.74 0 top
C2515  10U_0603_6.3V6M  [C_0603]  93.09 16.47 0 top
C2516  0.1U_0402_10V7K  [C_0402]  89.36 18.25 180 top
C2518  0.1U_0402_10V7K  [C_0402]  92.84 84.88 270 top
C2519  0.1U_0402_10V7K  [C_0402]  89.34 84.81 270 top
C2520  0.1U_0402_10V7K  [C_0402]  85.28 111.08 90 top
C2521  0.1U_0402_10V7K  [C_0402]  123.65 41.11 180 bottom
C2522  0.1U_0402_10V7K  [C_0402]  100.06 18.46 180 top
C2523  0.1U_0402_10V7K  [C_0402]  66.48 9.69 270 bottom
C2524  0.1U_0402_10V7K  [C_0402]  70.17 11.09 270 bottom
C2525  0.1U_0402_10V7K  [C_0402]  66.67 14.49 90 bottom
C2526  0.1U_0402_10V6K  [C_0402]  83.06 17.44 270 bottom
C2527  0.01U_0402_16V  [C_0402]  143.36 65.04 90 top
C2528  0.01U_0402_16V  [C_0402]  93.98 65.38 270 bottom
CC1  0.22U_0201_6.3V  [C_0201]  92.08 90.03 180 top
CC2  0.22U_0201_6.3V  [C_0201]  90.17 90.41 180 top
CC3  0.22U_0201_6.3V  [C_0201]  92.08 91.94 180 top
CC4  0.22U_0201_6.3V  [C_0201]  90.17 92.32 180 top
CC5  0.22U_0201_6.3V  [C_0201]  92.08 93.84 180 top
CC6  0.22U_0201_6.3V  [C_0201]  90.17 94.22 180 top
CC7  0.22U_0201_6.3V  [C_0201]  92.08 95.75 180 top
CC8  0.22U_0201_6.3V  [C_0201]  90.17 96.13 180 top
CC9  0.22U_0201_6.3V  [C_0201]  92.08 97.08 180 top
CC10  0.22U_0201_6.3V  [C_0201]  90.87 98.6 180 top
CC11  0.22U_0201_6.3V  [C_0201]  92.08 98.99 180 top
CC12  0.22U_0201_6.3V  [C_0201]  90.88 100.55 180 top
CC13  0.22U_0201_6.3V  [C_0201]  92.08 89.46 180 top
CC14  0.22U_0201_6.3V  [C_0201]  90.17 90.98 180 top
CC15  0.22U_0201_6.3V  [C_0201]  92.08 91.37 180 top
CC16  0.22U_0201_6.3V  [C_0201]  90.17 92.89 180 top
CC17  0.22U_0201_6.3V  [C_0201]  92.08 93.27 180 top
CC18  0.22U_0201_6.3V  [C_0201]  90.17 94.79 180 top
CC19  0.22U_0201_6.3V  [C_0201]  92.08 95.18 180 top
CC20  0.22U_0201_6.3V  [C_0201]  90.17 96.7 180 top
CC21  0.22U_0201_6.3V  [C_0201]  92.08 97.65 180 top
CC22  0.22U_0201_6.3V  [C_0201]  90.87 98.03 180 top
CC23  0.22U_0201_6.3V  [C_0201]  92.08 99.56 180 top
CC24  0.22U_0201_6.3V  [C_0201]  90.88 99.98 180 top
CC36  1U_0201_6.3V6M  [C_0201]  98.51 91.57 180 bottom
CC37  1U_0201_6.3V6M  [C_0201]  98.51 92.15 180 bottom
CC39  22U_0402_6.3V6M  [C_0402]  100.94 105.68 0 bottom
CC40  0.22U_0201_6.3V  [C_0201]  64.91 106.82 0 top
CC41  0.22U_0201_6.3V  [C_0201]  63.26 105.85 0 top
CC42  0.22U_0201_6.3V  [C_0201]  63.26 108.39 0 top
CC43  0.22U_0201_6.3V  [C_0201]  63.26 101.76 0 top
CC44  0.22U_0201_6.3V  [C_0201]  63.26 103.87 0 top
CC45  0.22U_0201_6.3V  [C_0201]  63.26 104.51 0 top
CC46  0.22U_0201_6.3V  [C_0201]  64.91 109.41 0 top
CC47  0.22U_0201_6.3V  [C_0201]  64.91 105.47 0 top
CC48  0.22U_0201_6.3V  [C_0201]  63.26 102.4 0 top
CC49  0.22U_0201_6.3V  [C_0201]  63.26 106.49 0 top
CC50  0.22U_0201_6.3V  [C_0201]  64.91 103.47 0 top
CC51  0.22U_0201_6.3V  [C_0201]  64.91 102.83 0 top
CC52  0.22U_0201_6.3V  [C_0201]  64.91 107.45 0 top
CC53  0.22U_0201_6.3V  [C_0201]  64.91 104.84 0 top
CC54  0.22U_0201_6.3V  [C_0201]  64.91 108.77 0 top
CC55  0.22U_0201_6.3V  [C_0201]  63.26 107.76 0 top
CD69  0.1U_0402_16V7K~D  [C_0402]  143.51 57.53 270 bottom
CD111  0.1U_0402_10V6K  [C_0402]  142.62 56.62 90 bottom
CD112  0.1U_0402_10V6K  [C_0402]  119 58.59 270 bottom
CD113  0.1U_0402_10V6K  [C_0402]  120.25 60.96 0 top
CD114  0.1U_0201_10V6K  [C_0201]  101.7 57.05 180 top
CD256  10U_0402_6.3V6M  [C_0402]  120.27 59.48 270 top
CD263  0.047U_0201_10V6K  [C_0201]  129.07 56.92 180 top
CD264  0.047U_0402_10V7K  [C_0402]  131.5 61.9 90 bottom
CD265  1U_0201_6.3V6M  [C_0201]  137.8 57.02 180 bottom
CD266  1U_0201_6.3V6M  [C_0201]  141.86 64.65 270 bottom
CD267  1U_0201_6.3V6M  [C_0201]  134.93 73.14 90 bottom
CD268  1U_0201_6.3V6M  [C_0201]  139.69 73.67 270 bottom
CD269  1U_0201_6.3V6M  [C_0201]  131.5 70.47 90 bottom
CD270  1U_0201_6.3V6M  [C_0201]  131.5 64.91 270 bottom
CD271  1U_0201_6.3V6M  [C_0201]  121.02 72.53 270 bottom
CD272  1U_0201_6.3V6M  [C_0201]  121.02 66.18 270 bottom
CD273  10U_0402_6.3V6M  [C_0402]  128.62 73.41 0 bottom
CD274  1U_0201_6.3V6M  [C_0201]  121.02 70.73 90 bottom
CD275  10U_0402_6.3V6M  [C_0402]  121.81 73.41 180 bottom
CD276  10U_0402_6.3V6M  [C_0402]  140.75 73.41 0 bottom
CD277  10U_0402_6.3V6M  [C_0402]  135.92 73.41 0 bottom
CD278  10U_0402_6.3V6M  [C_0402]  123.79 73.41 0 bottom
CD279  1U_0201_6.3V6M  [C_0201]  131.5 60.12 90 bottom
CD280  1U_0201_6.3V6M  [C_0201]  131.5 59.26 270 bottom
CD281  10U_0402_6.3V6M  [C_0402]  141.98 69.53 0 bottom
CD282  1U_0201_6.3V6M  [C_0201]  121.02 59.26 270 bottom
CD283  1U_0201_6.3V6M  [C_0201]  121.02 60.12 90 bottom
CD284  10U_0402_6.3V6M  [C_0402]  119.94 59.27 270 bottom
CD285  1U_0201_6.3V6M  [C_0201]  133.56 57.05 0 bottom
CD286  1U_0201_6.3V6M  [C_0201]  134.83 57.05 0 bottom
CD287  10U_0402_6.3V6M  [C_0402]  141.97 66.32 0 bottom
CD288  1U_0201_6.3V6M  [C_0201]  141.88 67.08 0 bottom
CD289  1U_0201_6.3V6M  [C_0201]  141.88 65.56 0 bottom
CD290  10U_0402_6.3V6M  [C_0402]  131.84 56.86 0 bottom
CD291  0.022U_0402_16V7K~D  [C_0402]  139.24 90.77 0 top
CD292  0.047U_0402_10V7K  [C_0402]  141.99 61 270 bottom
CD293  1U_0201_6.3V6M  [C_0201]  127.23 56.92 180 top
CD295  10U_0402_6.3V6M  [C_0402]  142.14 71.03 90 top
CD296  1U_0201_6.3V6M  [C_0201]  131.07 56.9 180 top
CD297  10U_0402_6.3V6M  [C_0402]  94.11 56.34 90 bottom
CD298  10U_0402_6.3V6M  [C_0402]  126.64 73.41 180 bottom
CD299  1U_0201_6.3V6M  [C_0201]  138.12 73.34 180 top
CD300  1U_0201_6.3V6M  [C_0201]  142.96 53.56 0 top
CD301  10U_0402_6.3V6M  [C_0402]  141.92 68.52 0 bottom
CD302  1U_0201_6.3V6M  [C_0201]  121.02 64.25 90 bottom
CD303  1U_0201_6.3V6M  [C_0201]  130.5 56.96 180 bottom
CD304  1U_0201_6.3V6M  [C_0201]  131.5 71.3 90 top
CD305  1U_0201_6.3V6M  [C_0201]  121.02 70.73 90 top
CD306  1U_0201_6.3V6M  [C_0201]  121.02 68.89 90 top
CD307  1U_0201_6.3V6M  [C_0201]  140.61 56.99 0 top
CD308  1U_0201_6.3V6M  [C_0201]  139.05 73.34 0 top
CD309  1U_0201_6.3V6M  [C_0201]  133.17 73.28 180 top
CD310  10U_0402_6.3V6M  [C_0402]  133.94 73.41 180 bottom
CD311  1U_0201_6.3V6M  [C_0201]  121.02 59.26 270 top
CD312  1U_0201_6.3V6M  [C_0201]  128.28 56.96 180 bottom
CD313  1U_0201_6.3V6M  [C_0201]  120.97 68.14 270 top
CD314  1U_0201_6.3V6M  [C_0201]  114.05 73.41 180 bottom
CD315  1U_0201_6.3V6M  [C_0201]  134.09 73.28 0 top
CD316  0.047U_0201_10V6K  [C_0201]  121.07 63.72 180 top
CD317  1U_0201_6.3V6M  [C_0201]  131.51 62.93 270 top
CD318  10U_0402_6.3V6M  [C_0402]  142.74 55.59 0 top
CD319  1U_0201_6.3V6M  [C_0201]  124.55 56.92 0 top
CD320  0.047U_0402_10V7K  [C_0402]  105.66 62.75 270 bottom
CD321  0.047U_0402_10V7K  [C_0402]  116.07 61.9 90 bottom
CD322  0.047U_0201_10V6K  [C_0201]  95.17 62.81 270 top
CD323  0.047U_0201_10V6K  [C_0201]  105.59 61.9 90 top
CD324  0.022U_0402_16V7K~D  [C_0402]  139.18 89.05 0 top
CD325  1U_0201_6.3V6M  [C_0201]  95.19 68.25 90 top
CD326  10U_0402_6.3V6M  [C_0402]  130.55 73.41 0 bottom
CD327  1U_0201_6.3V6M  [C_0201]  106.88 56.96 180 top
CD328  1U_0402_6.3V6K  [C_0402]  91.19 58.1 180 bottom
CD329  10U_0402_6.3V6M  [C_0402]  118.9 73.41 0 bottom
CD330  330U_D3_2.5VY_R6M  [C_X]  91.1 71.39 270 bottom
CD331  1U_0402_6.3V6K  [C_0402]  95.17 60.12 90 bottom
CD332  1U_0402_6.3V6K  [C_0402]  116.08 69.42 90 bottom
CD333  1U_0402_6.3V6K  [C_0402]  95.17 59.26 270 bottom
CD334  1U_0201_6.3V6M  [C_0201]  116.01 70.73 90 top
CD335  1U_0201_6.3V6M  [C_0201]  116.07 66.32 270 top
CD336  1U_0201_6.3V6M  [C_0201]  98.49 56.38 90 bottom
CD337  1U_0201_6.3V6M  [C_0201]  97.85 56.38 90 bottom
CD338  1U_0402_6.3V6K  [C_0402]  95.05 67.13 270 bottom
CD339  10U_0402_6.3V6M  [C_0402]  111.22 73.41 0 bottom
CD340  10U_0402_6.3V6M  [C_0402]  109.3 73.41 180 bottom
CD341  1U_0402_6.3V6K  [C_0402]  91.25 62.8 180 bottom
CD342  10U_0402_6.3V6M  [C_0402]  142.67 56.54 0 top
CD343  1U_0201_6.3V6M  [C_0201]  142.18 69.65 90 top
CD344  1U_0402_6.3V6K  [C_0402]  105.59 59.2 270 bottom
CD345  1U_0201_6.3V6M  [C_0201]  105.59 60.12 90 top
CD346  1U_0201_6.3V6M  [C_0201]  105.6 58.66 90 top
CD347  10U_0402_6.3V6M  [C_0402]  116.84 59.03 270 top
CD348  10U_0402_6.3V6M  [C_0402]  92.25 62.92 90 bottom
CD349  1U_0402_6.3V6K  [C_0402]  91.25 61.91 180 bottom
CD350  1U_0402_6.3V6K  [C_0402]  96.02 73.43 180 bottom
CD351  10U_0402_6.3V6M  [C_0402]  92.25 58.99 270 bottom
CD352  1U_0402_6.3V6K  [C_0402]  105.59 71.51 270 bottom
CD353  10U_0402_6.3V6M  [C_0402]  101.82 73.41 0 bottom
CD354  10U_0402_6.3V6M  [C_0402]  106.52 73.41 0 bottom
CD355  1U_0201_6.3V6M  [C_0201]  105.59 65.93 270 top
CD356  1U_0201_6.3V6M  [C_0201]  105.6 72.65 270 top
CD357  10U_0402_6.3V6M  [C_0402]  97.05 73.41 0 bottom
CD358  10U_0402_6.3V6M  [C_0402]  99.84 73.41 180 bottom
CD359  1U_0402_6.3V6K  [C_0402]  105.59 60.06 90 bottom
CD360  1U_0201_6.3V6M  [C_0201]  95.17 58.34 90 top
CD361  1U_0201_6.3V6M  [C_0201]  99.76 56.38 90 bottom
CD362  1U_0201_6.3V6M  [C_0201]  102.83 73.18 0 top
CD363  10U_0402_6.3V6M  [C_0402]  95.06 56.34 90 bottom
CD364  1U_0201_6.3V6M  [C_0201]  99.12 56.38 90 bottom
CD365  10U_0402_6.3V6M  [C_0402]  105.08 73.41 180 bottom
CD366  10U_0402_6.3V6M  [C_0402]  117.15 59.27 270 bottom
CD367  1U_0201_6.3V6M  [C_0201]  116.01 72 90 top
CD368  1U_0402_6.3V6K  [C_0402]  116.07 67.3 90 bottom
CD369  10U_0402_6.3V6M  [C_0402]  138.77 73.41 180 bottom
CD370  1U_0201_6.3V6M  [C_0201]  116.08 59.18 270 top
CD371  1U_0402_6.3V6K  [C_0402]  95.11 71.43 90 bottom
CD372  1U_0402_6.3V6K  [C_0402]  116.07 72.4 270 bottom
CD373  1U_0402_6.3V6K  [C_0402]  91.19 58.99 180 bottom
CD374  1U_0402_6.3V6K  [C_0402]  95.06 65.38 270 bottom
CD375  1U_0402_6.3V6K  [C_0402]  116.07 59.26 270 bottom
CD376  1U_0402_6.3V6K  [C_0402]  117.02 65.74 270 bottom
CD377  1U_0201_6.3V6M  [C_0201]  116.13 60.12 90 top
CD378  100P_0201_50V8J  [C_0201]  116.08 63.25 90 top
CD379  100P_0201_50V8J  [C_0201]  131.44 60.01 270 top
CD380  100P_0201_50V8J  [C_0201]  97.22 56.38 90 bottom
CD381  100P_0201_50V8J  [C_0201]  100.1 73.18 0 top
CD382  100P_0201_50V8J  [C_0201]  131.51 70.03 90 top
CD383  100P_0201_50V8J  [C_0201]  141.52 54.19 180 top
CD384  100P_0201_50V8J  [C_0201]  116.08 65.04 270 top
CD385  100P_0201_50V8J  [C_0201]  105.6 70.47 90 top
CD386  100P_0201_50V8J  [C_0201]  142.96 54.83 0 top
CD387  100P_0201_50V8J  [C_0201]  95.19 67.05 90 top
CD388  100P_0201_50V8J  [C_0201]  95.19 71.55 90 top
CD389  100P_0201_50V8J  [C_0201]  142.96 54.19 0 top
CD390  100P_0201_50V8J  [C_0201]  131.44 58.68 270 top
CD391  100P_0201_50V8J  [C_0201]  92.9 71.55 90 top
CD392  100P_0201_50V8J  [C_0201]  141.52 54.83 180 top
CD393  100P_0201_50V8J  [C_0201]  105.6 64 90 top
CD394  100P_0201_50V8J  [C_0201]  94.61 71.55 90 top
CD395  100P_0201_50V8J  [C_0201]  141.52 53.56 180 top
CD396  100P_0201_50V8J  [C_0201]  128.74 73.18 0 top
CD397  100P_0201_50V8J  [C_0201]  94.04 71.55 90 top
CD398  100P_0201_50V8J  [C_0201]  96.58 56.38 90 bottom
CD399  100P_0201_50V8J  [C_0201]  113.5 73.18 0 top
CD400  100P_0201_50V8J  [C_0201]  93.47 71.55 90 top
CD401  100P_0201_50V8J  [C_0201]  95.95 56.38 90 bottom
CD402  0.047U_0201_10V6K  [C_0201]  5.41 6.17 180 top
CE1  0.1U_0402_16V4Z  [C_0402]  127.52 26.97 90 bottom
CE2  15P_0402_50V  [C_0402]  128.27 23.07 90 bottom
CE5  15P_0402_50V  [C_0402]  128.28 19.76 270 bottom
CE6  0.1U_0402_16V4Z  [C_0402]  125.19 27.05 180 bottom
CE7  1U_0402_6.3V  [C_0402]  129.94 17.98 270 bottom
CE8  0.1U_0402_16V7K  [C_0402]  126.62 15.94 180 top
CE19  0.1U_0402_16V4Z~D  [C_0402]  115.96 15.65 180 bottom
CE20  22P_0402_50V8J~D  [C_0402]  125.11 13.51 90 bottom
CE22  4.7U_0603_10V  [C_0603]  134.62 15.52 270 bottom
CE27  0.1U_0402_16V7K  [C_0402]  10.16 18.94 90 bottom
CE28  0.1U_0402_10V7K  [C_0402]  73.41 17.06 270 top
CE29  0.1U_0402_10V7K  [C_0402]  82.28 20.69 180 top
CE30  0.1U_0402_10V7K  [C_0402]  86.58 8.37 90 top
CE31  1000P_0402_50V7K  [C_0402]  80.76 18.89 0 top
CE32  1000P_0402_50V7K  [C_0402]  83.83 18.89 180 top
CE34  .047U_0402_16V7K  [C_0402]  85.99 13.67 90 top
CE41  0.1U_0402_10V7K  [C_0402]  84.05 9.69 270 top
CE43  0.1U_0402_10V7K  [C_0402]  140.4 27.13 90 bottom
CE44  0.1U_0402_10V7K  [C_0402]  84.65 17.03 90 top
CE45  0.1U_0402_10V7K  [C_0402]  80 7.71 0 top
CE46  0.1U_0402_10V7K  [C_0402]  73.23 12.16 180 top
CE51  0.033U_0402_25V  [C_0402]  76.85 9.74 180 top
CE59  0.1U_0402_16V4Z  [C_0402]  126.63 26.97 90 bottom
CE60  0.1U_0402_16V4Z  [C_0402]  125.19 27.94 180 bottom
CE62  .1U_0402_16V7K  [C_0402]  88.66 19.86 90 bottom
CE63  0.1U_0402_16V7K~D  [C_0402]  92.93 16.38 180 bottom
CE64  0.1U_0402_16V7K  [C_0402]  115.97 23.82 270 bottom
CE65  10U_0402_6.3V6M  [C_0402]  128.41 26.97 90 bottom
CE79  0.1U_0402_10V6K  [C_0402]  78.68 21.8 90 top
CE81  0.1U_0402_10V6K  [C_0402]  83.11 22.51 0 top
CE86  0.1U_0402_16V4Z  [C_0402]  89.09 6.37 90 bottom
CE168  0.1U_0402_16V4Z  [C_0402]  106 18.27 90 bottom
CE169  0.1U_0402_16V4Z  [C_0402]  130.95 17.98 270 bottom
CE170  1U_0402_6.3V  [C_0402]  137.79 27.21 0 bottom
CE171  0.1U_0402_10V7K  [C_0402]  86.39 10.95 0 top
CE172  0.1U_0402_10V7K  [C_0402]  74.28 17.74 0 top
CE183  4.7U_0805_10V4Z  [C_0805]  83.5 23.62 90 top
CE184  0.1U_0402_10V6K  [C_0402]  83.11 21.61 0 top
CE186  0.1U_0402_16V7K  [C_0402]  81.67 19.78 180 top
CE189  100P_0402_50V8J  [C_0402]  74.16 13.81 0 top
CE190  100P_0402_50V8J  [C_0402]  76.57 18.95 0 top
CE191  0.1U_0402_10V7K  [C_0402]  74.09 10.63 0 top
CE192  0.1U_0402_10V7K  [C_0402]  87.05 11.81 90 top
CE193  0.1U_0402_10V7K  [C_0402]  111 15.45 90 top
CE194  0.1U_0402_10V7K  [C_0402]  133.16 15.53 270 bottom
CE195  0.1U_0402_16V7K  [C_0402]  83.11 20.68 0 top
CE196  0.1U_0402_16V7K  [C_0402]  76.16 17.69 270 bottom
CE197  0.1U_0402_16V7K  [C_0402]  75.23 17.69 270 bottom
CF4  10U_0603_25V6M  [C_0603]  15.68 48.03 270 bottom
CF5  22U_0805_25VAM  [C_0805]  17.02 49.56 0 bottom
CG1  22U_0603_4V_M  [C_0603]  63.56 103.53 0 bottom
CG2  22U_0603_4V_M  [C_0603]  64.64 106.9 0 bottom
CG3  22U_0603_4V_M  [C_0603]  55.82 105.06 90 bottom
CG4  22U_0603_4V_M  [C_0603]  54.48 105.06 90 bottom
CG5  10U_0603_4V_M  [C_0603]  66.04 108.17 180 bottom
CG6  10U_0603_4V_M  [C_0603]  64.96 104.8 180 bottom
CG7  10U_0603_4V_M  [C_0603]  55.44 114.52 270 bottom
CG8  10U_0603_4V_M  [C_0603]  60.9 101.44 180 bottom
CG9  10U_0603_4V_M  [C_0603]  60.9 98.77 180 bottom
CG10  10U_0603_4V_M  [C_0603]  60.96 104.1 180 bottom
CG11  1U_0201_4V6M  [C_0201]  52.58 93.28 180 bottom
CG12  1U_0201_4V6M  [C_0201]  59.82 113.53 90 bottom
CG13  1U_0201_4V6M  [C_0201]  53.24 109.19 180 bottom
CG14  1U_0201_4V6M  [C_0201]  63.63 113.53 90 bottom
CG15  1U_0201_4V6M  [C_0201]  62.36 113.53 90 bottom
CG16  1U_0201_4V6M  [C_0201]  53.24 109.79 180 bottom
CG17  1U_0201_4V6M  [C_0201]  52.62 90.99 180 bottom
CG18  1U_0201_4V6M  [C_0201]  52.62 91.56 180 bottom
CG19  0.47U_0201_4V_M  [C_0201]  52.62 92.7 180 bottom
CG20  0.47U_0201_4V_M  [C_0201]  52.55 97.12 180 bottom
CG21  0.47U_0201_4V_M  [C_0201]  63.97 100.87 0 bottom
CG22  0.47U_0201_4V_M  [C_0201]  63.97 102.58 0 bottom
CG23  0.47U_0201_4V_M  [C_0201]  52.62 92.13 180 bottom
CG24  0.47U_0201_4V_M  [C_0201]  63.97 100.29 0 bottom
CG25  0.47U_0201_4V_M  [C_0201]  63.97 101.44 0 bottom
CG26  0.47U_0201_4V_M  [C_0201]  63.97 102.01 0 bottom
CG27  4.7U_0402_4V_M  [C_0402]  53.22 108.35 180 bottom
CG28  4.7U_0402_4V_M  [C_0402]  53.22 107.33 180 bottom
CG29  4.7U_0402_4V_M  [C_0402]  53.22 106.43 180 bottom
CG30  1U_0201_4V6M  [C_0201]  51.92 103.53 180 bottom
CG31  1U_0201_4V6M  [C_0201]  48.81 90.14 90 bottom
CG32  1U_0201_4V6M  [C_0201]  49.42 90.14 90 bottom
CG33  1U_0201_4V6M  [C_0201]  49.87 88.94 90 bottom
CG34  1U_0201_4V6M  [C_0201]  48.7 88.94 90 bottom
CG35  1U_0201_4V6M  [C_0201]  50.6 90.15 90 bottom
CG36  0.47U_0201_4VAM  [C_0201]  50.03 90.14 90 bottom
CG37  0.47U_0201_4V_M  [C_0201]  51.01 88.96 90 bottom
CG38  0.47U_0201_4V_M  [C_0201]  50.42 88.94 90 bottom
CG39  0.47U_0201_4V_M  [C_0201]  49.28 88.94 90 bottom
CG40  0.47U_0201_4V_M  [C_0201]  52.55 100.17 180 bottom
CG41  0.47U_0201_4V_M  [C_0201]  52.55 98.9 180 bottom
CG42  4.7U_0402_4V_M  [C_0402]  52.46 101.91 180 bottom
CG43  4.7U_0402_4V_M  [C_0402]  52.46 101.02 180 bottom
CG45  4.7U_0402_4V_M  [C_0402]  52.46 102.8 180 bottom
CG59  1U_0201_4V6M  [C_0201]  30.31 103.98 0 bottom
CG60  1U_0201_4V6M  [C_0201]  30.31 103.34 0 bottom
CG61  1U_0201_4V6M  [C_0201]  45.56 111.29 270 bottom
CG62  22U_0603_4V_M  [C_0603]  49.41 110.95 90 bottom
CG63  4.7U_0402_4V_M  [C_0402]  48.16 110.95 90 bottom
CG64  4.7U_0402_4V_M  [C_0402]  46.89 110.95 90 bottom
CG65  1U_0201_4V6M  [C_0201]  30.73 94.43 270 bottom
CG66  0.1U_0402_16V4Z  [C_0402]  66.92 89.12 0 top
CG75  22P_0402_50V8J  [C_0402]  59.66 89.29 270 bottom
CG76  22P_0402_50V8J  [C_0402]  59.66 86.6 90 bottom
CG78  820P_0402_25V7  [C_0402]  28.65 130.46 270 bottom
CG101  10U_0603_4V_M  [C_0603]  25.3 127.38 0 bottom
CG102  10U_0603_4V_M  [C_0603]  41.97 138 180 bottom
CG103  10U_0603_4V_M  [C_0603]  41.97 135.44 180 bottom
CG104  10U_0603_4V_M  [C_0603]  42 131.52 180 bottom
CG105  10U_0603_4V_M  [C_0603]  35.2 138.13 0 bottom
CG106  10U_0603_4V_M  [C_0603]  41.97 136.67 180 bottom
CG107  22U_0603_4V_M  [C_0603]  40.56 139.3 0 bottom
CG108  22U_0603_4V_M  [C_0603]  36.61 139.35 180 bottom
CG109  22U_0603_4V_M  [C_0603]  26.69 128.99 180 bottom
CG110  22U_0603_4V_M  [C_0603]  26.69 125.9 180 bottom
CG111  22U_0603_4V_M  [C_0603]  26.67 138.72 90 top
CG112  22U_0603_4V_M  [C_0603]  41.97 125.76 90 bottom
CG148  820P_0402_25V7  [C_0402]  8.29 83.51 90 bottom
CG240  0.1U_0402_16V7K  [C_0402]  9.97 15.19 90 top
CG246  0.1U_0201_6.3V6K  [C_0201]  74.42 66.16 90 bottom
CG256  820P_0402_25V7  [C_0402]  43.05 70.31 0 bottom
CG270  2.2U_0402_6.3V6M  [C_0402]  66.99 98.4 270 top
CG312  1U_0201_4V6M  [C_0201]  52.55 99.53 180 bottom
CG322  1U_0402_6.3V6K  [C_0402]  9.97 17.03 90 top
CG323  0.1U_0402_16V7K  [C_0402]  8.48 18.98 0 top
CG384  0.1U_0402_10V7K  [C_0402]  3.38 14.67 180 top
CG385  10U_0402_6.3V6M  [C_0402]  8.48 19.93 0 top
CG476  0.1U_0201_6.3V6K  [C_0201]  73.79 66.16 90 bottom
CG478  0.1U_0201_6.3V6K  [C_0201]  6.32 2.76 180 top
CG481  2200P_0402_25V7K  [C_0402]  75.25 57.8 90 bottom
CG483  0.1U_0201_6.3V6K  [C_0201]  65.66 91.89 270 top
CG511  4.7U_0402_4V_M  [C_0402]  38.39 139.58 270 bottom
CG512  0.47U_0201_4V_M  [C_0201]  33.06 125.52 180 bottom
CG513  0.47U_0201_4V_M  [C_0201]  39.17 139.65 0 bottom
CG514  0.47U_0201_4V_M  [C_0201]  36.07 127.13 270 bottom
CG515  0.47U_0201_4V_M  [C_0201]  37.67 139.42 270 bottom
CG516  22U_0603_4V_M  [C_0603]  59.94 134.58 270 top
CG517  22U_0603_4V_M  [C_0603]  42.32 138.72 90 top
CG518  22U_0603_4V_M  [C_0603]  46.32 139.48 180 bottom
CG519  22U_0603_4V_M  [C_0603]  46.32 136.57 180 bottom
CG520  22U_0603_4V_M  [C_0603]  58.18 136.44 0 bottom
CG521  22U_0603_4V_M  [C_0603]  58.18 125.68 0 bottom
CG546  10U_0603_4V_M  [C_0603]  59.57 135.22 180 bottom
CG547  10U_0603_4V_M  [C_0603]  59.57 134 180 bottom
CG548  10U_0603_4V_M  [C_0603]  59.57 131.52 180 bottom
CG549  10U_0603_4V_M  [C_0603]  52.89 139.47 270 bottom
CG550  10U_0603_4V_M  [C_0603]  44.93 138.05 0 bottom
CG551  10U_0603_4V_M  [C_0603]  59.57 132.78 180 bottom
CG552  4.7U_0402_4V_M  [C_0402]  55.38 139.65 0 bottom
CG553  0.47U_0201_4V_M  [C_0201]  50.73 139.67 180 bottom
CG554  0.47U_0201_4V_M  [C_0201]  54.41 139.56 270 bottom
CG555  0.47U_0201_4V_M  [C_0201]  54.94 126.48 90 bottom
CG556  0.47U_0201_4V_M  [C_0201]  50.67 125.45 180 bottom
CG569  1U_0201_4V6M  [C_0201]  30.63 109.06 0 bottom
CG570  1U_0201_4V6M  [C_0201]  35.53 90.26 90 bottom
CG571  820P_0402_25V7  [C_0402]  7.03 118.2 90 bottom
CG573  10U_0603_4V_M  [C_0603]  9.24 112.16 180 bottom
CG574  10U_0603_4V_M  [C_0603]  9.24 113.39 180 bottom
CG575  10U_0603_4V_M  [C_0603]  13.18 119.78 270 bottom
CG576  10U_0603_4V_M  [C_0603]  3.43 116.04 0 bottom
CG577  10U_0603_4V_M  [C_0603]  4.35 103.29 90 bottom
CG578  10U_0603_4V_M  [C_0603]  5.84 116.04 0 bottom
CG579  22U_0603_4V_M  [C_0603]  14.41 118.38 90 bottom
CG580  22U_0603_4V_M  [C_0603]  15.63 118.38 90 bottom
CG581  22U_0603_4V_M  [C_0603]  5.56 102.56 270 bottom
CG582  22U_0603_4V_M  [C_0603]  11.87 112.15 180 bottom
CG583  22U_0603_4V_M  [C_0603]  3.13 102.57 270 bottom
CG584  22U_0603_4V_M  [C_0603]  7.85 110.94 0 bottom
CG621  0.47U_0201_4V_M  [C_0201]  16.07 109.98 270 bottom
CG622  0.47U_0201_4V_M  [C_0201]  2.74 111.56 0 bottom
CG623  0.47U_0201_4V_M  [C_0201]  2.66 113.19 0 bottom
CG624  0.47U_0201_4V_M  [C_0201]  16.07 113.91 90 bottom
CG625  4.7U_0402_4V_M  [C_0402]  2.79 112.34 0 bottom
CG638  10U_0603_4V_M  [C_0603]  7.45 128.22 180 bottom
CG639  10U_0603_4V_M  [C_0603]  7.45 129.44 180 bottom
CG640  10U_0603_4V_M  [C_0603]  10.97 128.61 90 bottom
CG641  10U_0603_4V_M  [C_0603]  9.72 132.62 270 bottom
CG642  10U_0603_4V_M  [C_0603]  12.15 121.54 90 bottom
CG643  10U_0603_4V_M  [C_0603]  14.3 128.61 90 bottom
CG644  22U_0603_4V_M  [C_0603]  9.72 130.01 270 bottom
CG645  22U_0603_4V_M  [C_0603]  4.38 122.34 270 bottom
CG646  22U_0603_4V_M  [C_0603]  12.18 130.01 270 bottom
CG647  22U_0603_4V_M  [C_0603]  13.4 122.94 270 bottom
CG648  22U_0603_4V_M  [C_0603]  3.15 122.34 270 bottom
CG649  22U_0603_4V_M  [C_0603]  15.52 130.01 270 bottom
CG674  0.47U_0201_4V_M  [C_0201]  16.07 127.07 270 bottom
CG676  0.47U_0201_4V_M  [C_0201]  16.07 130.93 90 bottom
CG677  0.47U_0201_4V_M  [C_0201]  2.45 130.14 0 bottom
CG678  4.7U_0402_4V_M  [C_0402]  2.52 129.34 0 bottom
CG679  22U_0603_4V_M  [C_0603]  25.12 60.36 270 bottom
CG680  22U_0603_4V_M  [C_0603]  4.83 81.94 180 bottom
CG681  10U_0603_4V_M  [C_0603]  22.67 58.96 90 bottom
CG682  22U_0603_4V_M  [C_0603]  5 72.37 270 bottom
CG683  22U_0603_4V_M  [C_0603]  2.57 72.38 270 bottom
CG684  10U_0603_4V_M  [C_0603]  5.91 80.42 90 bottom
CG685  10U_0603_4V_M  [C_0603]  3.79 70.98 90 bottom
CG686  10U_0603_4V_M  [C_0603]  23.89 58.96 90 bottom
CG687  22U_0603_4V_M  [C_0603]  7.85 78 0 bottom
CG688  10U_0603_4V_M  [C_0603]  9.24 79.23 180 bottom
CG689  10U_0603_4V_M  [C_0603]  9.24 76.78 180 bottom
CG690  22U_0603_4V_M  [C_0603]  11.87 77.99 180 bottom
CG718  0.47U_0201_4V_M  [C_0201]  3.45 78.07 0 bottom
CG722  0.47U_0201_4V_M  [C_0201]  3.29 76.54 0 bottom
CG723  0.47U_0201_4V_M  [C_0201]  3.45 79.21 0 bottom
CG726  0.47U_0201_4V_M  [C_0201]  3.45 78.64 0 bottom
CG727  4.7U_0402_4V_M  [C_0402]  3.42 77.31 0 bottom
CG732  10U_0603_4V_M  [C_0603]  6.79 101.19 90 bottom
CG733  22U_0603_4V_M  [C_0603]  7.85 96.31 0 bottom
CG734  22U_0603_4V_M  [C_0603]  7.85 95.08 0 bottom
CG735  10U_0603_4V_M  [C_0603]  9.24 101.19 90 bottom
CG736  10U_0603_4V_M  [C_0603]  5.56 84.08 90 bottom
CG737  22U_0603_4V_M  [C_0603]  8 102.59 270 bottom
CG738  22U_0603_4V_M  [C_0603]  4.84 99 180 bottom
CG739  10U_0603_4V_M  [C_0603]  4.35 84.08 90 bottom
CG740  22U_0603_4V_M  [C_0603]  11.87 95.07 180 bottom
CG741  22U_0603_4V_M  [C_0603]  7.18 98.99 180 bottom
CG742  10U_0603_4V_M  [C_0603]  3.13 84.1 90 bottom
CG743  10U_0603_4V_M  [C_0603]  9.24 93.86 180 bottom
CG768  0.47U_0201_4V_M  [C_0201]  3.64 96.23 0 bottom
CG769  0.47U_0201_4V_M  [C_0201]  16.13 92.97 270 bottom
CG770  4.7U_0402_4V_M  [C_0402]  2.55 94.95 0 bottom
CG771  0.47U_0201_4V_M  [C_0201]  11.47 97.12 180 bottom
CG772  0.47U_0201_4V_M  [C_0201]  7.07 91.91 0 bottom
CG773  0.47U_0201_4V_M  [C_0201]  11.47 97.75 180 bottom
CG774  0.47U_0201_4V_M  [C_0201]  8.92 91.17 0 bottom
CG775  0.47U_0201_4V_M  [C_0201]  16.13 96.89 90 bottom
CG776  0.47U_0201_4V_M  [C_0201]  4.47 100.23 0 bottom
CG777  0.47U_0201_4V_M  [C_0201]  16.07 99.7 270 bottom
CG778  0.47U_0201_4V_M  [C_0201]  2.35 93.1 0 bottom
CG779  0.47U_0201_4V_M  [C_0201]  14.25 100.17 0 bottom
CG780  0.47U_0201_4V_M  [C_0201]  6.18 100.23 0 bottom
CG781  0.47U_0201_4V_M  [C_0201]  2.46 95.68 0 bottom
CG782  0.47U_0201_4V_M  [C_0201]  8.04 100.23 180 bottom
CG783  0.47U_0201_4V_M  [C_0201]  11.4 92.02 180 bottom
CG784  0.47U_0201_4V_M  [C_0201]  8.57 98.36 270 bottom
CG785  10U_0603_4V_M  [C_0603]  54.17 63.46 90 bottom
CG786  10U_0603_4V_M  [C_0603]  49.45 68.24 270 bottom
CG787  22U_0603_4V_M  [C_0603]  50.66 66.85 90 bottom
CG788  22U_0603_4V_M  [C_0603]  50.66 69.5 90 bottom
CG789  10U_0603_4V_M  [C_0603]  49.45 70.89 270 bottom
CG790  22U_0603_4V_M  [C_0603]  48.17 61.32 270 bottom
CG791  22U_0603_4V_M  [C_0603]  47.12 62.32 90 bottom
CG792  22U_0603_4V_M  [C_0603]  46.35 72.23 90 bottom
CG793  10U_0603_4V_M  [C_0603]  46.91 59.92 90 bottom
CG794  10U_0603_4V_M  [C_0603]  49.38 59.92 90 bottom
CG795  10U_0603_4V_M  [C_0603]  50.6 59.92 90 bottom
CG796  22U_0603_4V_M  [C_0603]  45.91 68.8 0 bottom
CG823  0.47U_0201_4V_M  [C_0201]  52.06 75.77 0 bottom
CG826  0.47U_0201_4V_M  [C_0201]  49.47 62.21 90 bottom
CG827  4.7U_0402_4V_M  [C_0402]  50.24 62.21 90 bottom
CG835  0.47U_0201_4V_M  [C_0201]  48.11 75.08 180 bottom
CG837  0.47U_0201_4V_M  [C_0201]  51.46 62.21 90 bottom
CG838  22U_0603_4V_M  [C_0603]  30.86 70.32 0 bottom
CG839  22U_0603_4V_M  [C_0603]  33.3 66.85 90 bottom
CG840  10U_0603_4V_M  [C_0603]  44.15 64.87 180 bottom
CG841  22U_0603_4V_M  [C_0603]  37.66 69.24 0 bottom
CG842  22U_0603_4V_M  [C_0603]  25.46 84.86 0 bottom
CG843  10U_0603_4V_M  [C_0603]  44.15 63.64 180 bottom
CG844  10U_0603_4V_M  [C_0603]  44.15 62.42 180 bottom
CG845  10U_0603_4V_M  [C_0603]  26.28 62.19 0 bottom
CG846  10U_0603_4V_M  [C_0603]  26.28 63.4 0 bottom
CG847  22U_0603_4V_M  [C_0603]  25.46 86.07 0 bottom
CG848  10U_0603_4V_M  [C_0603]  26.29 64.62 0 bottom
CG849  22U_0603_4V_M  [C_0603]  34.51 66.85 90 bottom
CG878  0.47U_0201_4V_M  [C_0201]  36.6 75.08 0 bottom
CG882  0.47U_0201_4V_M  [C_0201]  31.98 75.08 180 bottom
